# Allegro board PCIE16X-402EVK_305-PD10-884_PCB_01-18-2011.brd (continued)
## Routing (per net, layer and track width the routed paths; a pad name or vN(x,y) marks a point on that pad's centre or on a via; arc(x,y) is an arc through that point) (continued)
N144872111: length 2.8
  TOP w0.292: SW3.6 v1(30.29,32.39)
  BOTTOM w0.292: R25.2 v1(30.29,32.39)
N144872810: length 2.8
  TOP w0.292: SW3.1 v1(17.59,32.39)
  BOTTOM w0.292: R20.2 v1(17.59,32.39)
N144872811: length 2.8
  TOP w0.292: 20.13,30.77 v1(20.13,32.39)
  BOTTOM w0.292: R21.2 v1(20.13,32.39)
N144872812: length 2.8
  TOP w0.292: SW3.3 v1(22.67,32.39)
  BOTTOM w0.292: R22.2 v1(22.67,32.39)
N144872813: length 2.8
  TOP w0.292: 25.21,30.77 v1(25.21,32.39)
  BOTTOM w0.292: R23.2 v1(25.21,32.39)
N144872814: length 2.8
  TOP w0.292: SW3.5 v1(27.75,32.39)
  BOTTOM w0.292: R24.2 v1(27.75,32.39)
N144873671: length 3.1
  TOP w0.292: SW5.4 v1(25.46,19.56)
  BOTTOM w0.292: R29.2 v1(25.46,19.56)
N144874091: length 3.1
  TOP w0.292: SW5.6 v1(30.54,19.56)
  BOTTOM w0.292: R31.2 v1(30.54,19.56)
N144874331: length 3.1
  TOP w0.292: 28,17.95 v1(28,19.56)
  BOTTOM w0.292: R30.2 v1(28,19.56)
N144874811: length 3.1
  TOP w0.292: 22.92,17.95 v1(22.92,19.56)
  BOTTOM w0.292: R28.2 v1(22.92,19.56)
N144875811: length 3.1
  TOP w0.292: 17.84,17.95 v1(17.84,19.56)
  BOTTOM w0.292: R26.2 v1(17.84,19.56)
N144876491: length 3.1
  TOP w0.292: SW5.2 v1(20.38,19.56)
  BOTTOM w0.292: R27.2 v1(20.38,19.56)
N144883340: length 2.3
  TOP w0.292: SW10.1 161.58,37.55 v1(160.06,37.55)
  BOTTOM w0.292: R38.2 160.05,37.56 v1(160.06,37.55)
N144883341: length 2.5
  TOP w0.292: v1(159.99,40.09) 161.58,40.09 SW10.2
  BOTTOM w0.292: v1(159.99,40.09) 159.98,40.1 R39.2
N144883342: length 2.3
  TOP w0.292: SW10.3 v1(160.03,42.64)
  BOTTOM w0.292: R40.2 v1(160.03,42.64)
N144883343: length 2.5
  TOP w0.292: SW10.4 161.58,45.2 161.55,45.2 161.54,45.18 159.83,45.18 v1(159.81,45.16)
  BOTTOM w0.292: v1(159.81,45.16) 159.78,45.18 R41.2
N144883344: length 2.7
  TOP w0.292: SW10.5 161.55,47.69 v1(159.92,47.69)
  BOTTOM w0.292: v1(159.92,47.69) 159.91,47.7 R42.2
N144883345: length 2.6
  TOP w0.292: SW10.6 161.58,50.25 v1(160.03,50.25)
  BOTTOM w0.292: R43.2 160.02,50.26 v1(160.03,50.25)
N144883781: length 2.8
  TOP w0.292: v1(160.88,18.72) 162.78,18.72 SW11.1
  BOTTOM w0.292: R44.2 160.87,18.73 v1(160.88,18.72)
N144885701: length 2.6
  TOP w0.292: SW6.4 149.38,57.24 147.77,57.24 v1(147.76,57.25)
  BOTTOM w0.292: R35.2 v1(147.76,57.25)
N144886021: length 2.8
  TOP w0.292: v1(160.9,21.26) 162.78,21.26 SW11.2
  BOTTOM w0.292: v1(160.9,21.26) 160.89,21.27 R45.2
N144886681: length 2.7
  TOP w0.292: SW6.6 v1(147.71,62.33)
  BOTTOM w0.254: v1(147.71,62.33) 147.7,62.34 R37.2
N144886921: length 2.7
  TOP w0.292: v1(147.79,59.79) SW6.5
  BOTTOM w0.292: v1(147.79,59.79) 147.78,59.8 R36.2
N144888121: length 2.5
  TOP w0.292: v1(147.74,54.7) 149.39,54.7 SW6.3
  BOTTOM w0.292: R34.2 v1(147.74,54.7)
N144888661: length 3
  TOP w0.292: v1(160.82,31.42) 162.78,31.42 SW11.6
  BOTTOM w0.292: R49.2 160.81,31.43 v1(160.82,31.42)
N144889101: length 2.9
  TOP w0.292: v1(160.95,23.8) 162.78,23.8 SW11.3
  BOTTOM w0.292: v1(160.95,23.8) 160.94,23.81 R46.2
N144890181: length 2.9
  TOP w0.292: v1(160.95,26.34) 162.78,26.34 SW11.4
  BOTTOM w0.292: R47.2 160.94,26.35 v1(160.95,26.34)
N144890984: length 2.9
  TOP w0.292: SW11.5 162.78,28.88 v1(160.95,28.88)
  BOTTOM w0.292: v1(160.95,28.88) 160.94,28.89 R48.2
N144891221: length 2.7
  TOP w0.292: v1(147.59,49.63) 149.39,49.63 SW6.1
  BOTTOM w0.292: R32.2 146.72,49.64 147.58,49.64 v1(147.59,49.63)
N144891941: length 2.7
  TOP w0.292: v1(147.89,52.17) 147.85,52.17 147.85,52.17 SW6.2
  BOTTOM w0.292: v1(147.89,52.17) 147.88,52.15 R33.2
N144905650: length 1.9
  TOP w0.254: R7.1 D1.2
N144909880: length 1.9
  TOP w0.292: R9.1 D3.2
N144912360: length 1.9
  TOP w0.254: R8.1 D2.2
N144914850: length 1.9
  TOP w0.292: R10.1 D4.2
N708449615: length 34.3
  TOP w0.203: C63.2 51.88,27.97 51.88,27.42 v1(51.65,27.19)
  BOTTOM w0.203: v1(51.65,27.19) 51.85,26.99 51.85,19.24 55.32,15.77 61.67,15.77 64.22,13.22 64.22,9.28 62.92,7.98 62.92,3.81 J1.A16
N708449616: length 34.3
  TOP w0.203: v1(52.57,27.19) 52.34,27.42 52.34,27.97 C64.2
  BOTTOM w0.203: v1(52.57,27.19) 52.31,26.94 52.31,19.43 55.51,16.23 61.86,16.23 64.68,13.41 64.68,9.09 63.38,7.79 63.38,3.81 J1.A17
N708449620: length 34.6
  TOP w0.203: v1(53.17,26.56) 53.4,26.79 53.4,27.97 C65.2
  BOTTOM w0.203: v1(53.17,26.56) 53.38,26.35 53.38,20.53 56.44,17.47 62.71,17.47 67.92,12.26 67.92,3.81 J1.A21
N708449621: length 34.7
  TOP w0.203: C66.2 53.86,27.97 53.86,26.79 v1(54.09,26.56)
  BOTTOM w0.203: J1.A22 68.38,3.81 68.38,12.45 62.9,17.93 56.63,17.93 53.84,20.72 53.84,26.3 v1(54.09,26.56)
N708449624: length 34.9
  TOP w0.203: v1(54.7,27.19) 54.93,27.42 54.93,27.97 C67.2
  BOTTOM w0.203: J1.A25 71.92,3.81 71.92,10.91 63.43,19.4 58.4,19.4 54.95,22.85 54.95,26.94 v1(54.7,27.19)
N708449625: length 34.9
  TOP w0.203: v1(55.61,27.19) 55.39,27.42 55.39,27.97 C68.2
  BOTTOM w0.203: v1(55.61,27.19) 55.41,26.99 55.41,23.03 58.59,19.86 63.61,19.86 72.38,11.1 72.38,3.81 J1.A26
N708449628: length 35
  TOP w0.203: C69.2 56.45,27.97 56.45,26.79 v1(56.22,26.56)
  BOTTOM w0.203: J1.A29 75.92,3.81 75.92,6.53 75.17,7.27 75.17,9.74 63.73,21.18 60.28,21.18 56.43,25.03 56.43,26.35 v1(56.22,26.56)
N708449629: length 35.1
  TOP w0.203: v1(57.14,26.56) 56.91,26.79 56.91,27.97 C70.2
  BOTTOM w0.203: v1(57.14,26.56) 56.88,26.3 56.88,25.22 60.47,21.64 63.92,21.64 75.63,9.93 75.63,7.46 76.38,6.71 76.38,3.81 J1.A30
N708449634: length 34.4
  TOP w0.203: v1(67.65,27.19) 67.88,27.42 67.88,27.97 C71.2
  BOTTOM w0.203: J1.A35 81.92,3.81 81.92,11.37 78.56,14.73 72.29,14.73 67.86,19.16 67.86,26.99 v1(67.65,27.19)
N708449635: length 34.5
  TOP w0.203: C72.2 68.34,27.97 68.34,27.42 v1(68.57,27.19)
  BOTTOM w0.203: J1.A36 82.38,3.81 82.38,11.56 78.75,15.19 72.48,15.19 68.31,19.35 68.31,26.94 v1(68.57,27.19)
N708449638: length 34.9
  TOP w0.203: v1(69.18,26.56) 69.41,26.79 69.41,27.97 C73.2
  BOTTOM w0.203: v1(69.18,26.56) 69.41,26.33 69.41,20.94 73.79,16.56 79.17,16.56 85.92,9.81 85.92,3.81 J1.A39
N708449639: length 34.9
  TOP w0.203: C74.2 69.86,27.97 69.86,26.79 v1(70.09,26.56)
  BOTTOM w0.203: v1(70.09,26.56) 69.86,26.33 69.86,21.13 73.98,17.01 79.36,17.01 86.38,10 86.38,3.81 J1.A40
N708449642: length 35.1
  TOP w0.203: C75.2 70.93,27.97 70.93,27.42 v1(70.7,27.19)
  BOTTOM w0.203: v1(70.7,27.19) 70.93,26.96 70.93,23.02 75.46,18.49 79.43,18.49 89.92,7.99 89.92,3.81 J1.A43
N708449643: length 35.1
  TOP w0.203: C76.2 71.39,27.97 71.39,27.42 v1(71.62,27.19)
  BOTTOM w0.203: v1(71.62,27.19) 71.39,26.96 71.39,23.21 75.65,18.95 79.62,18.95 90.38,8.18 90.38,3.81 J1.A44
N708449646: length 35.2
  TOP w0.203: v1(72.22,26.56) 72.45,26.79 72.45,27.97 C77.2
  BOTTOM w0.203: J1.A47 93.92,3.81 93.92,6.66 80.09,20.49 77.75,20.49 72.48,25.77 72.48,26.3 v1(72.22,26.56)
N708449647: length 35.2
  TOP w0.203: v1(73.14,26.56) 72.91,26.79 72.91,27.97 C78.2
  BOTTOM w0.203: J1.A48 94.38,3.81 94.38,6.85 80.28,20.95 77.94,20.95 72.94,25.96 72.94,26.35 v1(73.14,26.56)
N708449651: length 34.3
  TOP w0.203: v1(102.22,27.19) 102.45,27.42 102.45,27.97 C79.2
  BOTTOM w0.203: v1(102.22,27.19) 102.45,26.96 102.45,16.49 101.63,15.67 96.06,15.67 95.06,14.66 95.06,8.82 95.94,7.95 98.45,7.95 98.92,7.48 98.92,3.81 J1.A52
N708449652: length 34.3
  TOP w0.203: v1(103.14,27.19) 102.91,27.42 102.91,27.97 C80.2
  BOTTOM w0.203: v1(103.14,27.19) 102.91,26.96 102.91,16.3 101.82,15.21 96.25,15.21 95.52,14.47 95.52,9.01 96.13,8.4 98.64,8.4 99.38,7.67 99.38,3.81 J1.A53
N708449655: length 34.7
  TOP w0.203: C81.2 103.98,27.97 103.98,26.79 v1(103.75,26.56)
  BOTTOM w0.203: v1(103.75,26.56) 103.98,26.33 103.98,15.48 102.62,14.12 98.25,14.12 97.19,13.06 97.19,10.58 98.2,9.57 101.6,9.57 102.92,8.25 102.92,3.81 J1.A56
N708449656: length 34.7
  TOP w0.203: C82.2 104.43,27.97 104.43,26.79 v1(104.66,26.56)
  BOTTOM w0.203: v1(104.66,26.56) 104.43,26.33 104.43,15.29 102.81,13.66 98.44,13.66 97.65,12.87 97.65,10.77 98.39,10.03 101.79,10.03 103.38,8.44 103.38,3.81 J1.A57
N708449659: length 34.9
  TOP w0.203: C83.2 105.5,27.97 105.5,27.42 v1(105.27,27.19)
  BOTTOM w0.203: J1.A60 106.92,3.81 106.92,7.83 105.45,9.31 105.45,17.76 107.06,19.38 110.72,19.38 111.29,19.95 111.29,22.29 110.62,22.96 106.57,22.96 105.52,24 105.52,26.94 v1(105.27,27.19)
N708449660: length 34.9
  TOP w0.203: C84.2 105.96,27.97 105.96,27.42 v1(106.19,27.19)
  BOTTOM w0.203: J1.A61 107.38,3.81 107.38,8.02 105.91,9.5 105.91,17.57 107.25,18.92 110.91,18.92 111.75,19.76 111.75,22.48 110.81,23.42 106.76,23.42 105.98,24.19 105.98,26.99 v1(106.19,27.19)
N708449663: length 35.2
  TOP w0.203: C85.2 107.02,27.97 107.02,26.79 v1(106.79,26.56)
  BOTTOM w0.203: v1(106.79,26.56) 107.02,26.33 107.02,25.28 107.85,24.46 112.19,24.46 113.02,23.63 113.02,19.13 111.86,17.98 109.35,17.98 107.48,16.11 107.48,10.53 110.92,7.09 110.92,3.81 J1.A64
N708449664: length 35.2
  TOP w0.203: v1(107.71,26.56) 107.48,26.79 107.48,27.97 C86.2
  BOTTOM w0.203: J1.A65 111.38,3.81 111.38,7.27 107.94,10.72 107.94,15.92 109.54,17.52 112.05,17.52 113.47,18.95 113.47,23.82 112.38,24.91 108.04,24.91 107.48,25.47 107.48,26.33 v1(107.71,26.56)
N708449667: length 34.4
  TOP w0.203: C87.2 118.45,27.97 118.45,27.42 v1(118.22,27.19)
  BOTTOM w0.203: J1.A68 114.92,3.81 114.92,7.68 114.07,8.53 112.04,8.53 110.17,10.4 110.17,14.89 112.04,16.76 116.94,16.76 118.45,18.27 118.45,26.96 v1(118.22,27.19)
N708449668: length 34.4
  TOP w0.203: v1(119.14,27.19) 118.91,27.42 118.91,27.97 C88.2
  BOTTOM w0.203: v1(119.14,27.19) 118.91,26.96 118.91,18.08 117.13,16.3 112.23,16.3 110.63,14.7 110.63,10.59 112.23,8.99 114.26,8.99 115.38,7.87 115.38,3.81 J1.A69
N708449671: length 34.8
  TOP w0.203: C89.2 119.98,27.97 119.98,26.79 v1(119.75,26.56)
  BOTTOM w0.203: J1.A72 118.92,3.81 118.92,9.02 117.6,10.33 114.2,10.33 113.07,11.47 113.07,14.13 114.17,15.24 118.58,15.24 119.98,16.63 119.98,26.33 v1(119.75,26.56)
N708449672: length 34.8
  TOP w0.203: v1(120.66,26.56) 120.43,26.79 120.43,27.97 C90.2
  BOTTOM w0.203: J1.A73 119.38,3.81 119.38,9.21 117.79,10.79 114.39,10.79 113.53,11.66 113.53,13.94 114.36,14.78 118.77,14.78 120.43,16.44 120.43,26.33 v1(120.66,26.56)
N708449675: length 34.9
  TOP w0.203: v1(121.27,27.19) 121.5,27.42 121.5,27.97 C91.2
  BOTTOM w0.203: v1(121.27,27.19) 121.48,26.99 121.48,17.36 122.45,16.38 127.56,16.38 128.21,15.73 128.21,13.8 127.59,13.18 124.18,13.18 122.92,11.92 122.92,3.81 J1.A76
N708449676: length 34.9
  TOP w0.203: C92.2 121.96,27.97 121.96,27.42 v1(122.19,27.19)
  BOTTOM w0.203: J1.A77 123.38,3.81 123.38,11.73 124.37,12.72 127.78,12.72 128.66,13.61 128.66,15.92 127.75,16.84 122.64,16.84 121.93,17.55 121.93,26.94 v1(122.19,27.19)
N708449679: length 35.1
  TOP w0.203: v1(122.8,26.56) 123.03,26.79 123.03,27.97 C93.2
  BOTTOM w0.203: v1(122.8,26.56) 123.05,26.3 123.05,19.11 124.26,17.9 128.7,17.9 130.11,16.5 130.11,12.68 129.11,11.68 126.24,11.68 125.01,10.45 125.01,8.62 126.92,6.71 126.92,3.81 J1.A80
N708449680: length 35.1
  TOP w0.203: C94.2 123.48,27.97 123.48,26.79 v1(123.71,26.56)
  BOTTOM w0.203: v1(123.71,26.56) 123.51,26.35 123.51,19.3 124.45,18.36 128.89,18.36 130.57,16.68 130.57,12.49 129.3,11.22 126.43,11.22 125.46,10.26 125.46,8.81 127.38,6.9 127.38,3.81 J1.A81
N708449695: length 32.4
  TOP w0.203: J1.B14 60.92,3.81 60.92,8.86 58.66,11.12 55.23,11.12 52.64,13.71 52.64,21.28 57.98,26.62 57.98,27.97 C31.1
N708449696: length 32.4
  TOP w0.203: C32.1 58.43,27.97 58.43,26.43 53.1,21.09 53.1,13.9 55.42,11.58 58.85,11.58 61.38,9.05 61.38,3.81 J1.B15
N7084496100: length 32.4
  TOP w0.203: C33.1 59.5,27.97 59.5,26.13 55.79,22.42 55.79,14.86 57.98,12.67 61.18,12.67 65.91,7.94 65.91,3.79 J1.B19
N7084496101: length 32.4
  TOP w0.203: J1.B20 66.36,3.82 66.36,8.13 61.37,13.13 58.17,13.13 56.25,15.05 56.25,22.24 59.96,25.94 59.96,27.97 C34.1
N7084496104: length 32.3
  TOP w0.203: C35.1 61.02,27.97 61.02,25.17 58.23,22.37 58.23,16.11 59.92,14.42 62.54,14.42 69.89,7.07 69.89,3.77 J1.B23
N7084496105: length 32.3
  TOP w0.203: C36.1 61.48,27.97 61.48,24.98 58.69,22.18 58.69,16.3 60.11,14.88 62.73,14.88 70.35,7.26 70.35,3.84 J1.B24
N7084496108: length 31.9
  TOP w0.203: J1.B27 73.9,3.79 73.9,7.25 64.95,16.2 62.74,16.2 61.1,17.84 61.1,22.98 62.55,24.43 62.55,27.97 C37.1
N7084496109: length 32
  TOP w0.203: J1.B28 74.36,3.83 74.36,7.44 65.14,16.66 62.93,16.66 61.56,18.03 61.56,22.79 63.01,24.24 63.01,27.97 C38.1
N7084496114: length 32.6
  TOP w0.203: J1.B33 79.88,3.76 79.88,7.78 78.59,9.06 74.5,9.06 70.35,13.22 70.35,22.84 73.98,26.48 73.98,27.97 C39.1
N7084496115: length 32.6
  TOP w0.203: J1.B34 80.33,3.85 80.33,7.97 78.78,9.52 74.69,9.52 70.8,13.41 70.8,22.65 74.44,26.29 74.44,27.97 C40.1
N7084496118: length 32.4
  TOP w0.203: C41.1 75.5,27.97 75.5,25.98 72.86,23.34 72.86,14.49 76.56,10.79 80.01,10.79 83.88,6.92 83.88,3.77 J1.B37
N7084496119: length 32.5
  TOP w0.203: C42.1 75.96,27.97 75.96,25.79 73.32,23.15 73.32,14.68 76.75,11.25 80.2,11.25 84.34,7.11 84.34,3.84 J1.B38
N7084496122: length 32.3
  TOP w0.203: C43.1 77.03,27.97 77.03,24.39 75.63,23 75.63,15.83 78.61,12.85 81.84,12.85 87.89,6.8 87.89,3.78 J1.B41
N7084496123: length 32.3
  TOP w0.203: C44.1 77.48,27.97 77.48,24.2 76.09,22.81 76.09,16.02 78.8,13.31 82.03,13.31 88.35,6.99 88.35,3.84 J1.B42
N7084496126: length 32
  TOP w0.203: J1.B45 91.96,3.85 91.96,6.8 83.93,14.83 81.05,14.83 78.55,17.33 78.55,27.96 78.4,28.11 C45.1
N7084496127: length 32
  TOP w0.203: C46.1 79.01,27.97 79.01,17.52 81.24,15.29 84.12,15.29 92.42,6.99 92.42,3.77 J1.B46
N7084496131: length 32.2
  TOP w0.203: J1.B50 96.94,3.83 96.94,7.58 102.43,13.06 102.43,23.29 103.42,24.28 107.93,24.28 108.55,24.9 108.55,27.97 C47.1
N7084496132: length 32.2
  TOP w0.203: J1.B51 97.4,3.79 97.4,7.39 102.88,12.87 102.88,23.1 103.61,23.82 108.12,23.82 109,24.71 109,27.97 C48.1
N7084496135: length 32.3
  TOP w0.203: J1.B54 100.93,3.81 100.93,7.12 105.58,11.77 105.58,13.57 103.82,15.33 103.82,21.61 104.84,22.63 108.8,22.63 110.07,23.9 110.07,27.97 C49.1
N7084496136: length 32.3
  TOP w0.203: J1.B55 101.38,3.8 101.38,6.93 106.03,11.58 106.03,13.76 104.28,15.52 104.28,21.42 105.03,22.17 108.99,22.17 110.53,23.71 110.53,27.97 C50.1
N7084496139: length 32.1
  TOP w0.203: J1.B58 104.94,3.83 104.94,6.99 108.29,10.35 108.29,13.2 105.37,16.13 105.37,19.86 106.62,21.1 110.25,21.1 111.6,22.45 111.6,27.97 C51.1
N7084496140: length 32.1
  TOP w0.203: C52.1 112.05,27.97 112.05,22.26 110.44,20.65 106.81,20.65 105.83,19.67 105.83,16.32 108.75,13.39 108.75,10.16 105.4,6.8 105.4,3.79 J1.B59
N7084496143: length 32.1
  TOP w0.203: J1.B62 108.97,3.85 108.97,7.78 110.63,9.45 110.63,15.02 109.98,15.67 108.24,15.67 107.28,16.63 107.28,18.54 108.24,19.5 111.39,19.5 113.12,21.23 113.12,27.97 C53.1
N7084496144: length 32.1
  TOP w0.203: C54.1 113.58,27.97 113.58,21.04 111.58,19.05 108.43,19.05 107.73,18.35 107.73,16.82 108.43,16.13 110.17,16.13 111.09,15.21 111.09,9.26 109.42,7.59 109.42,3.76 J1.B63
N7084496147: length 32.6
  TOP w0.203: C55.1 124.55,27.97 124.55,26.51 123.28,25.24 118.11,25.24 114.97,22.11 114.97,10.56 112.92,8.51 112.92,3.8 J1.B66
N7084496148: length 32.6
  TOP w0.203: J1.B67 113.37,3.81 113.37,8.32 115.43,10.37 115.43,21.92 118.3,24.79 123.47,24.79 125.01,26.32 125.01,27.97 C56.1
N7084496151: length 32.1
  TOP w0.203: C57.1 126.07,27.97 126.07,25.1 124.82,23.85 118.73,23.85 116.93,22.04 116.93,3.82 J1.B70
N7084496152: length 32.1
  TOP w0.203: C58.1 126.53,27.97 126.53,24.91 125.01,23.39 118.92,23.39 117.39,21.85 117.39,3.8 J1.B71
N7084496155: length 32.2
  TOP w0.203: C59.1 127.6,27.97 127.6,23.82 125.87,22.09 120.87,22.09 118.89,20.11 118.89,9.67 120.94,7.62 120.94,3.83 J1.B74
N7084496156: length 32.1
  TOP w0.203: C60.1 128.05,27.97 128.05,23.63 126.06,21.64 121.06,21.64 119.34,19.92 119.34,9.86 121.4,7.81 121.4,3.79 J1.B75
N7084496159: length 31.9
  TOP w0.203: J1.B78 124.93,3.82 124.93,7.24 121.09,11.07 121.09,18.21 123.13,20.24 126.95,20.24 129.12,22.41 129.12,27.94 128.97,28.09 C61.1
N7084496160: length 31.9
  TOP w0.203: C62.1 129.58,27.97 129.58,22.22 127.14,19.78 123.32,19.78 121.55,18.02 121.55,11.26 125.39,7.43 125.39,3.8 J1.B79

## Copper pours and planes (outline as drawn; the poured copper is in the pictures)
12V on POWER2: 34.1,5.28 34.1,13.53 33.38,13.53 33.38,58.54 48.62,58.54 48.62,21 50.6,19.02 50.6,5.91 45.75,5.91 45.75,10.95 43.16,13.53 40.57,10.95 40.57,5.28
GND on BOTTOM: 55.76,36.98 60.78,36.98 61.29,36.47 61.29,32.92 60.91,32.54 54.23,32.54 53.36,33.41 53.36,34.43 54.66,35.73 54.66,36.73 54.81,36.88 54.85,36.88 55.66,36.88
GND on BOTTOM: 105.41,36.9 111.06,36.9 111.73,36.24 111.73,33.51 110.85,32.64 104.98,32.64 103.67,33.94 103.67,34.49 104.25,35.07 104.25,35.74
GND on BOTTOM: 126.04,36.93 126.88,36.09 126.88,36.09 127.13,35.84 127.13,35.54 127.77,34.9 127.77,32.82 127.5,32.56 124.18,32.56 124,32.38 120.17,32.38 119.66,32.88 119.66,36.28 120.31,36.93
GND on BOTTOM: 70.52,32.64 69.13,34.03 69.13,34.51 70.29,35.67 70.29,36.6 70.59,36.9 77.06,36.9 77.18,36.78 77.18,32.75 77.07,32.64
GND on GND1, GND2: 132.88,3.73 132.82,3.79 132.82,7.62 130.68,9.75 128.55,7.62 128.55,5.91 58.86,5.91 58.86,7.47 57.15,9.18 55.44,7.47 55.44,5.91 45.75,5.91 45.75,10.95 43.16,13.53 40.57,10.95 40.57,5.28 34.1,5.28 34.1,13.53 14.24,13.53 14.24,5.28 0.76,5.28 0.76,67.06 42.28,67.06 42.28,58.54 131.66,58.54 131.66,67.06 166.88,67.06 166.88,13.53 140.79,13.53 139.01,12.8 138.28,11.02 138.28,9.72 139.01,7.94 140.79,7.21 143.99,7.21 143.99,5.59 142.92,3.73
VDD1 on POWER2: 65.3,21.17 58.36,28.1 49.25,28.1 49.25,39.96 66.7,39.96 66.7,35.82 66.68,35.79 66.68,29.89 69.48,27.09 83.96,27.09 84.76,26.28 84.76,21.17
VDD2 on POWER2: 85.4,24.65 85.4,26.54 84.22,27.72 69.74,27.72 67.31,30.15 67.31,35.53 67.34,35.55 67.34,39.96 77.38,39.96 81.62,35.72 91.27,35.72 92.61,34.38 92.61,25.5 91.75,24.65
VDD3 on POWER2: 101.91,30.31 101.91,42.9 99.56,45.25 95.94,45.25 94.5,43.8 89.45,43.8 89.94,44.29 89.94,50.08 91.58,51.72 113.01,51.72 116.92,47.82 116.92,31.45 115.78,30.31
VDD4 on POWER2: 118.81,30.18 117.55,31.45 117.55,48.08 113.28,52.36 91.32,52.36 89.31,50.34 89.31,44.55 88.55,43.8 84.96,43.8 83.03,45.72 83.03,58.54 130.53,58.54 130.53,32.41 128.3,30.18
3_3V on TOP: 80.45,38.38 80.45,37.11 81.09,36.47 83.63,36.47 83.76,36.6 83.76,37.61 83.63,37.74 81.72,37.74 81.09,38.38
3_3V on POWER2: 51.23,5.91 51.23,14.61 87.95,14.61 88.65,15.31 88.65,17.88 88.08,18.45 86.68,18.45 85.4,19.74 85.4,24.01 92.02,24.01 93.24,25.24 93.24,34.65 91.53,36.36 81.88,36.36 77.64,40.6 49.25,40.6 49.25,58.54 82.4,58.54 82.4,45.46 84.69,43.16 94.76,43.16 96.21,44.61 99.3,44.61 101.27,42.64 101.27,22.2 100.21,21.14 96.63,21.14 95.66,20.17 95.66,5.91 58.86,5.91 58.86,7.47 57.15,9.18 55.44,7.47 55.44,5.91
VIH on POWER1: 85.03,22.25 125.41,22.25 129.86,26.69 136.72,26.69 137.99,25.42 137.99,17.01 137.3,16.33 128.56,16.33 123.18,10.94 85.33,10.94 85.03,11.25
VIH on POWER1: 9.36,16.15 50.33,16.15 50.66,16.48 50.66,25.47 50.33,25.8 23.05,25.8 21.4,27.45 21.4,30.38 25.84,34.82 25.84,50.19 24.96,51.08 8.83,51.08 6.39,48.64 6.39,19.12
VIH on POWER2: 0.76,5.28 0.76,60.4 32.74,60.4 32.74,13.53 14.24,13.53 14.24,5.28
VIH on POWER2: 132.88,3.73 132.82,3.79 132.82,7.62 130.68,9.75 128.55,7.62 128.55,5.91 96.29,5.91 96.29,19.91 96.89,20.51 100.47,20.51 101.91,21.94 101.91,29.68 116.04,29.68 117.23,30.87 118.55,29.55 128.57,29.55 131.17,32.15 131.17,58.54 166.88,58.54 166.88,13.53 140.79,13.53 139.01,12.8 138.28,11.02 138.28,9.72 139.01,7.94 140.79,7.21 143.99,7.21 143.99,5.59 142.92,3.73
VIH on POWER2: 51.23,15.25 51.23,19.28 49.25,21.26 49.25,27.47 58.1,27.47 65.03,20.53 84.76,20.53 84.76,19.47 86.42,17.81 87.82,17.81 88.01,17.62 88.01,15.57 87.69,15.25 ; 1 cut-out
VOUT1_2 on TOP: 89.98,18.97 92.06,18.97 92.44,18.59 92.44,17.93 92.8,17.57 93.31,17.57 93.33,17.6 93.76,17.6 93.92,17.45 94.91,17.45 95.19,17.73 95.19,21.54 93.31,23.42 86.53,23.42 85.31,24.63 85.31,26.44 86.17,27.3 99.25,27.3 100.01,26.54 100.01,16.66 98.11,14.75 90.49,14.75 89.65,15.59 89.65,18.64
VOUT3_4 on TOP: 87.31,37.61 89.29,37.61 89.99,36.92 91.2,36.92 91.28,36.99 92.35,36.99 92.52,37.16 92.52,41.07 91.31,42.28 88.19,42.28 87.39,43.08 87.39,45.56 88.05,46.22 95.19,46.22 96.03,45.39 96.03,36.24 95.26,35.48 93.43,35.48 92.47,34.52 87.57,34.52 86.98,35.1 86.98,37.28

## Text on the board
BOTTOM: BOTTOM
Ref Des/Assembly Bottom: A1 | A82 | BOTTOM ASSEMBLY
Board Geometry/Soldermask Bottom: BOTTOM MASK
Ref Des/Silkscreen Bottom: A | C | B | D | G | E | H | F | A1 | A82 | BOTTOM SILK | MADE IN U.S. | UL94V-0 | JAN 2011 | 305-PD-10-884
User.Comments: 2713 | 2535 | 2122 | 591 | 2250 | 1955 | 459 | 144 | 6600 | 2841 | 2949 | 3224 | 354 | 2XR69 | 500 | 55 | 189 | 386
TOP: TOP
Ref Des/Assembly Top: B1 | B82 | TOP ASSEMBLY
Board Geometry/Soldermask Top: TOP MASK
Ref Des/Silkscreen Top: 1-VDD3 | 2-2.5V | 3-2.5V | 4-VDD4 | J6 | 1-GND | 2-NC | 3-SCL | 4-SDA | J8 | 1-3_3V | 2-VIN3_4 | J5 | 4-VDD2 | 1-VDD1 | J4 | SD_TH/LPBK-RES | A_D1-RD_EN2 TO A_D4-PRSNT | READ_EN/RD_EN2 | EQA0/EQA1 | DEMA0/DEMA1 | ENSMB | DEMB0_AD1/DEMB1_AD0 | EQB0_AD2/EQB1_AD2 | SDA/SCL | SMCLK-SCL/SMDAT-SDA | VDD_SEL1_2/VDD_SEL3_4 | READ_EN | RXDET/RATE | 4.99K_GND | 249_VIH | 249_GND | OFF | 1 | 3 | 2 | 4 | 6 | 5 | 7 | 9 | 8 | 10 | 12 | 11 | ON | SIG | B1 | C | A | B | D | 2.5V | 3_3V | VIN1_2 | VIH | E | G | F | H | B82 | PRSNT | PCIe16X_402EVK REV1.0. | TOP SILK
GND1: GND1
POWER1: POWER1
POWER2: POWER2
GND2: GND2
DISPLAY_TOP: BOTTOM PASTE
DISPLAY_BOTTOM: TOP PASTE
User.7: 7 MIL | 1.4 MIL | 31.6 MIL | 4 MIL | SILKSCREEN (BOTTOM SIDE) | SOLDERMASK (BOTTOM SIDE) | SOLDERMASK (TOP SIDE) | SILKSCREEN (TOP SIDE) | GND1 | POWER1 | PREPEG | BOTTOM - COPPER + PLATING = 1.4 MIL FINISHED THICKNESS | GND2 | TOP - COPPER + PLATING = 1.4 MIL FINISHED THICKNESS TOP | POWER2 | CORE | TITLE: | C | NOTES: (UNLESS OTHERWISE SPECIFIED) | ~~~~~~~~~~~~~~~~~~~~~~~~~~~~~~~~~~~~~~~~~ | 17. IMPEDANCE DETAILS: | 16. ANY CHANGES MADE TO THE FILM OR GERBERS MUST BE APPROVED BY PACTRON. | 15. BOARD DIMENSION ARE IN INCHES. | 10. NO VENDOR LOGO OR NAME ON THE BOARD | 12. TOOLING HOLE: SHALL BE DRILLED FIRST AND PLUGGED DURING PLATING. | 13. REMOVE NON FUNCTIONAL PADS ON INNER LAYERS. | 11.DRILLING: | 14. CLIP THE SILKSCREEN OVER SOLDERMASK. | 1.BOARD THICKNESS: 62 MILS +2/-0 TOL | 2.MATERIAL:FR4 | 3.ALL COPPER LAYERS SHALL BE 1 OUNCE (1.4 MIL) FINISHED THICKNESS. | 4.FINISH: | 5.SOLDERMASK : LPI GREEN (MAINTAIN THICKNESS 1 MIL ON BOTH SIDES). | 6.SILK SCREENS BOTH SIDES SHALL BE WHITE. | 7.BOARD TWIST AND WARP SHALL NOT EXCEED 4MILS/LINEAR INCH | 8.EACH ASSEMBLED BOARD MUST BE PACKAGED IN A ESD BAG AND SEALED WITH AN ESD LABEL | 9.FINISHED BOARD IS ROHS COMPLIANT AND LEAD FREE. | 11.5 MIL TRACES IN ALL LAYERS REQUIRE 50 OHM IMPEDANCE +/-5 %TOL | 8 MIL TRACE WIDTH WITH 10 MIL AIRGAP IN TOP AND BOTTOM REQUIRES 100 OHM DIFFERENTIAL CONTROLLED IMPEDANCE  +/-5 % TOL | 11.1 ALL HOLE DIAMETERS ARE FINISHED SIZES. | 11.2 ALL HOLES TO BE +/- .003 FROM TRUE POSITION UNLESS OTHERWISE SPECIFIED. | 4A .HARD GOLD (25-40 MICRONS) OVER HARD NICKEL PLATING BOTH SIDES. | 4B .REST OF THE CIRCUITRY WILL BE SOFT IMMERSION GOLD | 4C .HARD GOLD (10-15 MICRONS) OVER HARD NICKEL PLATING BOTH SIDES. | LAYER STACKUP-6 LAYERS | FILM LAYERS ARE SHOWN AS | VIEWED FROM THE TOP SIDE | OF THE BOARD. | REVISIONS | DATE | DRAWN | QC | 1149 Tasman Drive, | JAN 2011 | PCIe16X-402EVK | DATED | 408 747 1239 (fax) | Sunnyvale Ca 94089 | UNITS: | 305-PD-10-884 | ,408 747 1237 (phone) | REV | SIZE | 1
User.9: FIGURE | SIZE | 10.0 | 39.37 | 40.0 | 125.0 | DRILL CHART: TOP to BOTTOM | ALL UNITS ARE IN MILS | TOLERANCE | +3.0/-3.0 | PLATED | QTY | 454 | 20 | 2 | 8 | 19
User.15: NOT TO SCALE | 2 X 0.02X45deg | 0.531 | 0.039 TYP. | 3.4250 | DETAIL-A | 0.039 | 0.200 | 0.276 MAX | 30deg | 0.020 | 0.062 | +0.000 | +0.002 | FAB | CHAMBER EDGES MUST BE FREE OF CUTTING BURRS | DETAIL-A & 4C | EDGE CONNECTOR | TYP0.062 | PROFILE | DETAIL-B & 4A | TYP 20 deg | FINGER DETAIL | TYP 0.051 | DETAIL-B | .5mm X 45 DEGREES
User.17: 1149 Tasman Drive, | Sunnyvale Ca 94089 | ,408 747 1237 (phone) | 408 747 1239 (fax) | NAME: PCIe16X_402EVK BOARD | DATE: JAN 2011 | LAYER | LAYER: | JOB: | 305-PD-10-884 | REV:1
User.24: GND1#2
User.26: PWR#4
User.27: GND2#5
